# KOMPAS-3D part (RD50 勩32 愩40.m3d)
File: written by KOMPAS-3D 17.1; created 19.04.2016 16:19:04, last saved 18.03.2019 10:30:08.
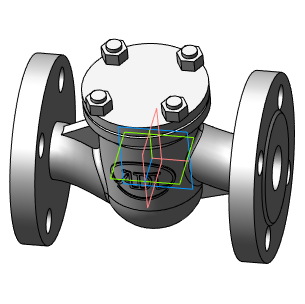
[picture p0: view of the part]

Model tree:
1. Операция без истории:2  (labels: Сталь 20  ГОСТ 1050-88)

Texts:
  RD50 Ду15 Ру40
  RD50 Ду20 Ру40
  RD50 Ду25 Ру40
  RD50 Ду32 Ру40
  RD50 Ду40 Ру40
  RD50 Ду50 Ру40
  RD50 Ду65 Ру40
  RD50 Ду80 Ру40
  RD50 Ду100 Ру40
  RD50 Ду125 Ру40
  RD50 Ду150 Ру40
  RD50 Ду200 Ру40
  RD50 Ду250 Ру40
  RD50 Ду300 Ру40
  RD50 Ду350 Ру40
  RD50 Ду400 Ру40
